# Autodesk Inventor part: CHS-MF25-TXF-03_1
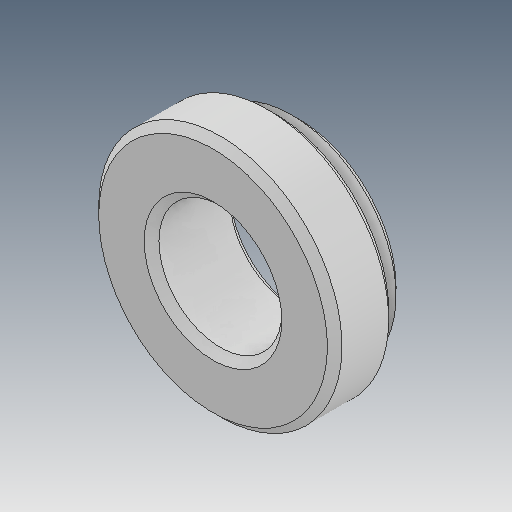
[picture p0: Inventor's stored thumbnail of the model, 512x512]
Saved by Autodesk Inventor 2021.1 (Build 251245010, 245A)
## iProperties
Created: 2019-04
Part Number: CHS-MF25-TXF-03_1
Material: Ogólny
Document SubType Name: Modeling
Designer: user
Density: 1 g/cm^3
Appearance: Domyślna
Author: user
Revision Number: ÈÎºÎ
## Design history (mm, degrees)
feature "ÊäÈë1"
node "Bryła1"
